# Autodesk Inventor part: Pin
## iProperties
Created: 2009-03
Part Number: Pin
Material: Steel
Document SubType Name: Modeling
Designer: tangg
Density: 7.85 g/cm^3
Author: tangg
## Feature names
1. Extrusion1
2. Revolution1
3. Mirror1
